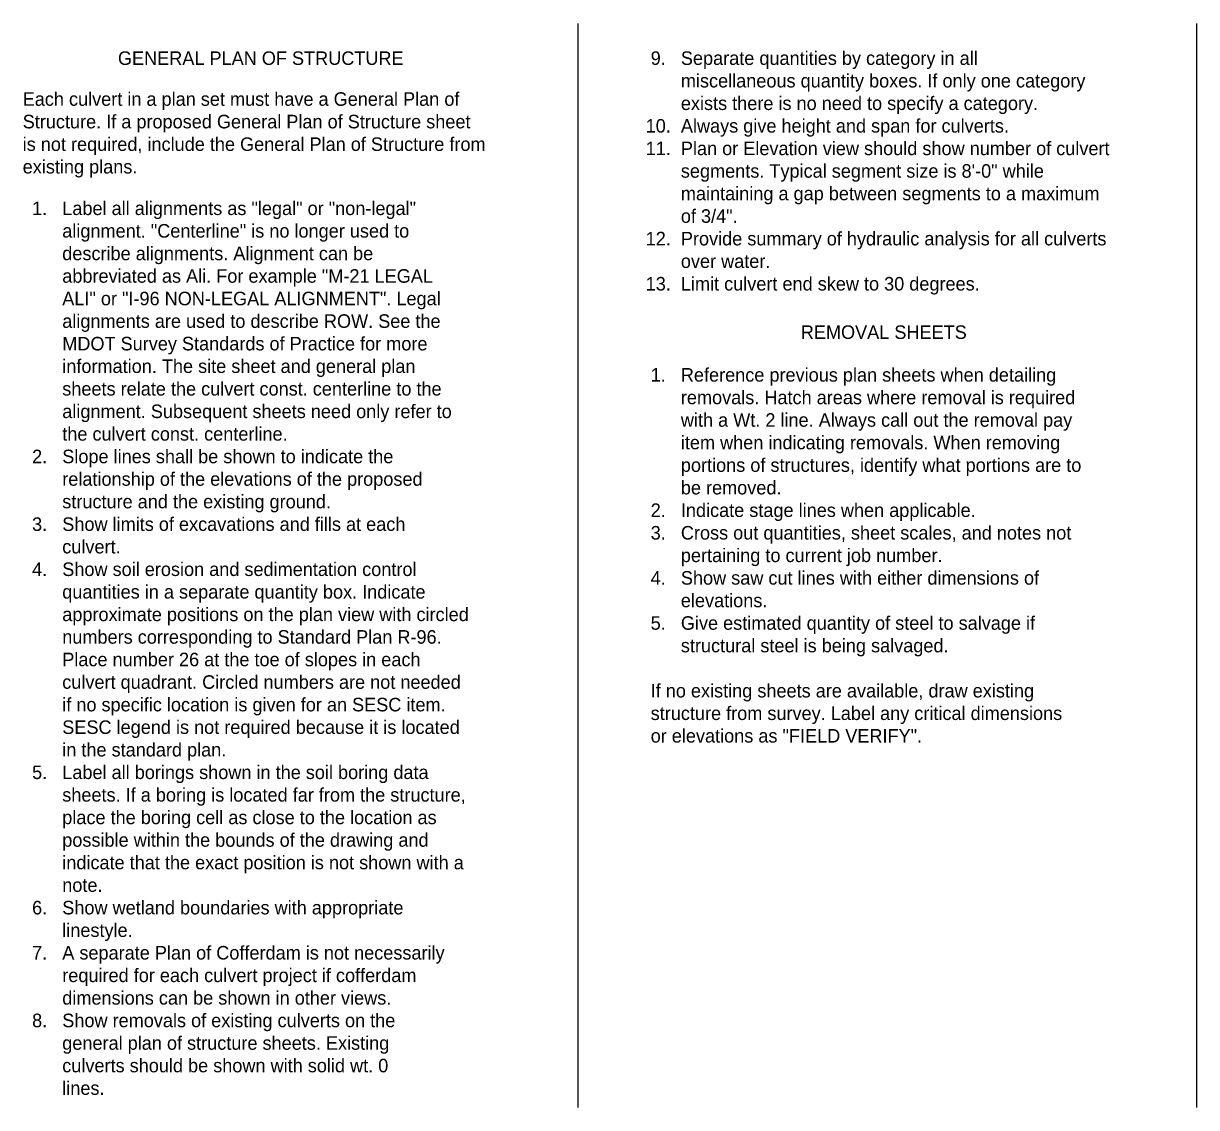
# Model space of a CAD drawing. Extents: x -1.12 to 1.46, y -0.08 to 0.96.
# Drawn here: x -1.116 to -0.249, y 0.058 to 0.859 of the extents above; entities that cross this region are included whole.
import ezdxf

# ---------------------------------------------------------------- set-up
doc = ezdxf.new("R2010")
doc.units = 0
doc.layers.add('Sheet_Label_Str_Wt0', color=7, linetype='Continuous')
doc.layers.add('Sheet_Label_Str_Wt2', color=7, linetype='Continuous')

msp = doc.modelspace()

# ---------------------------------------------------------------- linework, layer by layer
at = {"layer": 'Sheet_Label_Str_Wt0'}
for p, q in [((-0.7062, 0.85879), (-0.7062, 0.05788)), ((-0.24926, 0.85879), (-0.24926, 0.05788))]:
    msp.add_line(p, q, dxfattribs=at)

# ---------------------------------------------------------------- texts
for s, p in [('GENERAL PLAN OF STRUCTURE', (-1.04599, 0.82816)), ('REMOVAL SHEETS', (-0.54158, 0.62574))]:
    msp.add_text(s, height=0.01, dxfattribs=at).set_placement(p)
at = {"layer": 'Sheet_Label_Str_Wt2'}
for s, p in [('     9.   Separate quantities by category in all ', (-0.67104, 0.82816)), ('           miscellaneous quantity boxes. If only one category ', (-0.67104, 0.81149)), ('Each culvert in a plan set must have a General Plan of', (-1.11634, 0.79795)), ('           exists there is no need to specify a category.', (-0.67104, 0.79483)), ('Structure. If a proposed General Plan of Structure sheet ', (-1.11634, 0.78128)), ('    10.  Always give height and span for culverts.', (-0.67104, 0.77816)), ('is not required, include the General Plan of Structure from ', (-1.11634, 0.76461)), ('    11.  Plan or Elevation view should show number of culvert', (-0.67104, 0.76149)), ('existing plans.', (-1.11634, 0.74795)), ('           segments. Typical segment size is 8\'-0" while', (-0.67104, 0.74483)), ('           maintaining a gap between segments to a maximum ', (-0.67104, 0.72816)), ('     1.   Label all alignments as "legal" or "non-legal" ', (-1.12798, 0.71724)), ('           of 3/4". ', (-0.67104, 0.71149)), ('           alignment. "Centerline" is no longer used to ', (-1.12798, 0.70057)), ('    12.  Provide summary of hydraulic analysis for all culverts', (-0.67104, 0.69483)), ('           describe alignments. Alignment can be ', (-1.12798, 0.6839)), ('           over water.', (-0.67104, 0.67816)), ('           abbreviated as Ali. For example "M-21 LEGAL ', (-1.12798, 0.66724)), ('    13.  Limit culvert end skew to 30 degrees.', (-0.67104, 0.66149)), ('           ALI" or "I-96 NON-LEGAL ALIGNMENT". Legal ', (-1.12798, 0.65057)), ('           alignments are used to describe ROW. See the ', (-1.12798, 0.6339)), ('           MDOT Survey Standards of Practice for more ', (-1.12798, 0.61724)), ('           information. The site sheet and general plan', (-1.12798, 0.60057)), ('     1.   Reference previous plan sheets when detailing', (-0.67104, 0.59418)), ('           sheets relate the culvert const. centerline to the', (-1.12798, 0.5839)), ('           removals. Hatch areas where removal is required', (-0.67104, 0.57751)), ('           alignment. Subsequent sheets need only refer to', (-1.12798, 0.56724)), ('           with a Wt. 2 line. Always call out the removal pay', (-0.67104, 0.56085)), ('           the culvert const. centerline.', (-1.12798, 0.55057)), ('           item when indicating removals. When removing', (-0.67104, 0.54418)), ('     2.   Slope lines shall be shown to indicate the ', (-1.12798, 0.5339)), ('           portions of structures, identify what portions are to', (-0.67104, 0.52751)), ('           relationship of the elevations of the proposed ', (-1.12798, 0.51724)), ('           be removed.', (-0.67104, 0.51085)), ('           structure and the existing ground.', (-1.12798, 0.50057)), ('     2.   Indicate stage lines when applicable.', (-0.67104, 0.49418)), ('     3.   Show limits of excavations and fills at each', (-1.12798, 0.4839)), ('     3.   Cross out quantities, sheet scales, and notes not', (-0.67104, 0.47751)), ('           culvert.', (-1.12798, 0.46724)), ('           pertaining to current job number.', (-0.67104, 0.46085)), ('     4.   Show soil erosion and sedimentation control', (-1.12798, 0.45057)), ('     4.   Show saw cut lines with either dimensions of ', (-0.67104, 0.44418)), ('           quantities in a separate quantity box. Indicate', (-1.12798, 0.4339)), ('           elevations.', (-0.67104, 0.42751)), ('           approximate positions on the plan view with circled', (-1.12798, 0.41724)), ('     5.   Give estimated quantity of steel to salvage if', (-0.67104, 0.41085)), ('           numbers corresponding to Standard Plan R-96. ', (-1.12798, 0.40057)), ('           structural steel is being salvaged.', (-0.67104, 0.39418)), ('           Place number 26 at the toe of slopes in each ', (-1.12798, 0.3839)), ('           culvert quadrant. Circled numbers are not needed ', (-1.12798, 0.36724)), ('     If no existing sheets are available, draw existing', (-0.67104, 0.36085)), ('           if no specific location is given for an SESC item. ', (-1.12798, 0.35057)), ('     structure from survey. Label any critical dimensions', (-0.67104, 0.34418)), ('           SESC legend is not required because it is located ', (-1.12798, 0.3339)), ('     or elevations as "FIELD VERIFY".', (-0.67104, 0.32751)), ('           in the standard plan.', (-1.12798, 0.31724)), ('     5.   Label all borings shown in the soil boring data ', (-1.12798, 0.30057)), ('           sheets. If a boring is located far from the structure, ', (-1.12798, 0.2839)), ('           place the boring cell as close to the location as ', (-1.12798, 0.26724)), ('           possible within the bounds of the drawing and ', (-1.12798, 0.25057)), ('           indicate that the exact position is not shown with a ', (-1.12798, 0.2339)), ('           note.', (-1.12798, 0.21724)), ('     6.   Show wetland boundaries with appropriate ', (-1.12798, 0.20057)), ('           linestyle.', (-1.12798, 0.1839)), ('     7.   A separate Plan of Cofferdam is not necessarily', (-1.12798, 0.16724)), ('           required for each culvert project if cofferdam', (-1.12798, 0.15057)), ('           dimensions can be shown in other views.', (-1.12798, 0.1339)), ('     8.   Show removals of existing culverts on the', (-1.12798, 0.11724)), ('           general plan of structure sheets. Existing ', (-1.12798, 0.10057)), ('           culverts should be shown with solid wt. 0 ', (-1.12798, 0.0839)), ('           lines.', (-1.12798, 0.06724))]:
    msp.add_text(s, height=0.01, dxfattribs=at).set_placement(p)

doc.saveas('drawing.dxf')
